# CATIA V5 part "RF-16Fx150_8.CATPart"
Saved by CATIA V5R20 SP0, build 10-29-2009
Part number: _RF-16Fx150
Definition: NONE
Nomenclature: _RF-16Fx150
Source: Unknown
Description: PART-_RF-16Fx150-DESC
Bounding box of the stored display mesh (mm): x -150 to 27.5, y -8.75 to 8.75, z -8.75 to 8.75
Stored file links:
  C:\Users\Utente\Desktop\IO LAVORO\3D X SITO CF\X SITO\PLASTICA\RFF\RF-16Fx150_8.CATPart

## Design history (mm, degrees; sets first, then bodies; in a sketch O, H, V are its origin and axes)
Body1 "_RF-16Fx150" (main body)
  Solid1: solid without history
